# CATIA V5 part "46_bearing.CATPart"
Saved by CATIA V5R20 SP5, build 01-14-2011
Part number: 46_bearing
Bounding box of the stored display mesh (mm): x -14.994 to 14.994, y 125.368 to 155.356, z -128.5 to -120.5
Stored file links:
  C:\Documents and Settings\anizard\Bureau\13\46_bearing.CATPart
  C:\Documents and Settings\anizard\Bureau\13\anizard.CATProduct
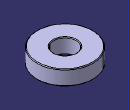
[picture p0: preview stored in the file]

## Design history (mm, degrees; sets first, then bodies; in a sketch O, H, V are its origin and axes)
Set1
  Plane1: linked copy from another document
  Plane2: linked copy from another document
  Point1: linked copy from another document
  Line1: linked copy from another document
  Plane3: linked copy from another document
  Point2: linked copy from another document
Body1 (main body)
  Sketch1 on Plane1, origin (0, 0, 0), H (0, 1, 0), V (0, 0, 1)
    line L1 (146.7155, -120.5) -> (155.0084, -120.5)
    line L2 (155.3619, -120.8536) -> (155.3619, -128.1464)
    line L3 (155.0084, -128.5) -> (146.7155, -128.5)
    line L4 (146.3619, -128.1464) -> (146.3619, -120.8536)
    line L5 (155.3619, -128.1464) -> (155.0084, -128.5)
    line L6 (155.0084, -120.5) -> (155.3619, -120.8536)
    line L7 (146.7155, -120.5) -> (146.3619, -120.8536)
    line L8 (146.7155, -128.5) -> (146.3619, -128.1464)
    reference intersected line E1 through (0, -128.5) direction (-1, 0) from Plane3
    reference projected point E2 (146.3619, -122.5) from Point2
    reference intersected line E3 through (0, -120.5) direction (-1, 0) from Plane2
    reference projected point E4 (155.3619, -122.5) from Point1
    angle L2 L5 = 45
    length L5 = 0.5
    angle L1 L6 = 45
    length L6 = 0.5
    angle L1 L7 = 45
    length L7 = 0.5
    angle L3 L8 = 45
    length L8 = 0.5
    horizontal: L1 H, L3 H
    vertical: L2 V, L4 V
    coincidence: L3 E1, L4 E2, L1 E3, E4 L2
  Shaft1: profile Sketch1, axis Line1, angle 360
